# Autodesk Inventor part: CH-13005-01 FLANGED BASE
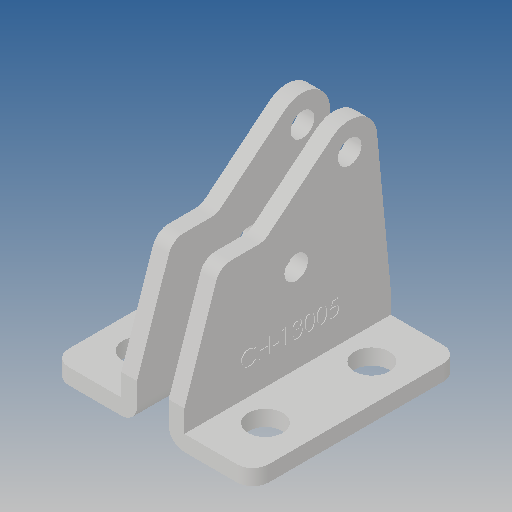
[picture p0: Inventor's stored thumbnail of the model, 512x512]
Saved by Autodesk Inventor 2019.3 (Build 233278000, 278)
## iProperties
Created: 2012-09
Part Number: CH-13005-01 FLANGED BASE
Material: Ogólny
Document SubType Name: Modeling
Designer: CADENGINEERING4
Density: 1 g/cm^3
Appearance: Domyślna
Author: CADENGINEERING4
Revision Number: ÈÎºÎ
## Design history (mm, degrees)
feature "ÇÐ³ý-À­Éì5"
feature "ÇÐ³ý-À­Éì8"
node "Bryła1"
node "Bryła2"
